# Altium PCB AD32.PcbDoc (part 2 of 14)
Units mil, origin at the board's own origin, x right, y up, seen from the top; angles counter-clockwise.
Board outline 7007.87 x 4368.85 mil, 12 copper layers (Top Layer, Int1 (GND), Int2 (AVDD), Int3 (DVDD), Int4 (GND), Int5 (ST), Int6 (SB), Int8 (AGND), Int7 (AVCC), Int9 (VCCA), Int10 (GND), Bottom Layer), stack 60.136 mil thick; 1350 components, 880 nets, 4712 pads, 2835 vias.
Unrouted connection lines stored in the file: 19.
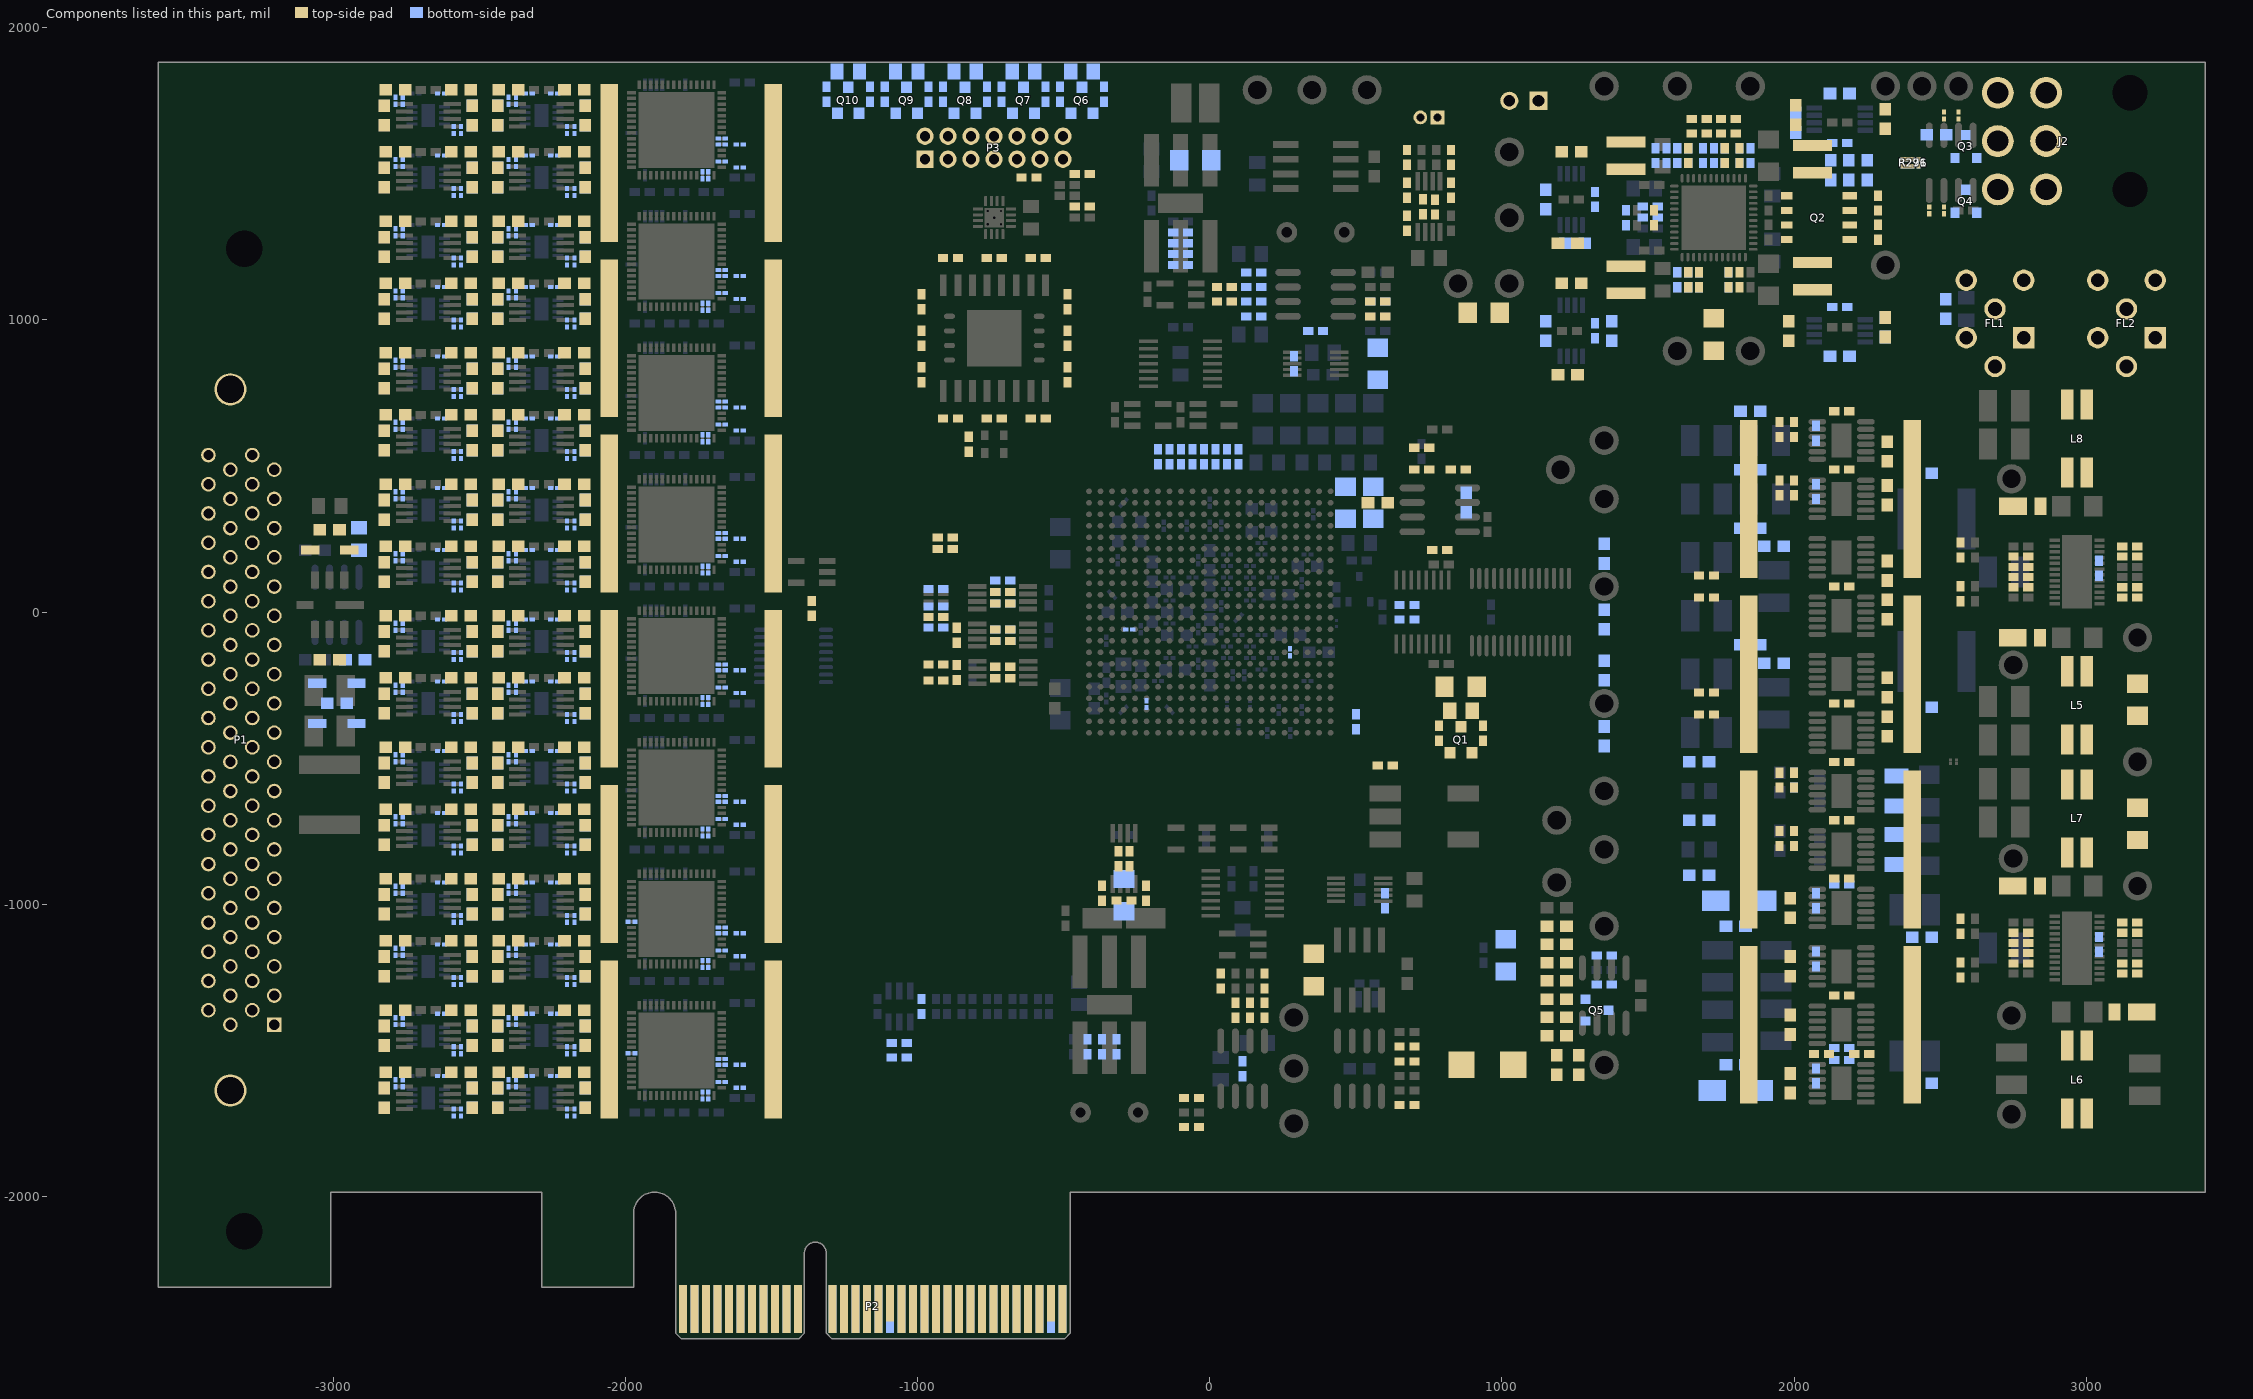
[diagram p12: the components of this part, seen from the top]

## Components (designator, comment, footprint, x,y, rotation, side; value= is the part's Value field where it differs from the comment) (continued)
C383G "1.0u" CC0603-0201 -1979.62,-1059.84 r180 bottom value=1u (schematic designator C383)
C383H "1.0u" CC0603-0201 -1979.62,-1509.84 r180 bottom value=1u (schematic designator C383)
C384A "100n" CC0603-0201 -2175,1437.5 r90 bottom (schematic designator C384)
C384B "100n" CC0603-0201 -2175,987.5 r90 bottom (schematic designator C384)
C384C "100n" CC0603-0201 -2175,537.5 r90 bottom (schematic designator C384)
C384D "100n" CC0603-0201 -2175,87.5 r90 bottom (schematic designator C384)
C384E "100n" CC0603-0201 -2175,-362.5 r90 bottom (schematic designator C384)
C384F "100n" CC0603-0201 -2175,-812.5 r90 bottom (schematic designator C384)
C384G "100n" CC0603-0201 -2175,-1262.5 r90 bottom (schematic designator C384)
C384H "100n" CC0603-0201 -2175,-1712.5 r90 bottom (schematic designator C384)
C385A "100n" CC0603-0201 -2200,1650 r90 bottom (schematic designator C385)
C385B "100n" CC0603-0201 -2200,1200 r90 bottom (schematic designator C385)
C385C "100n" CC0603-0201 -2200,750 r90 bottom (schematic designator C385)
C385D "100n" CC0603-0201 -2200,300 r90 bottom (schematic designator C385)
C385E "100n" CC0603-0201 -2200,-150 r90 bottom (schematic designator C385)
C385F "100n" CC0603-0201 -2200,-600 r90 bottom (schematic designator C385)
C385G "100n" CC0603-0201 -2200,-1050 r90 bottom (schematic designator C385)
C385H "100n" CC0603-0201 -2200,-1500 r90 bottom (schematic designator C385)
C400A "100n" CC0603-0201 -2400,1537.5 r90 bottom (schematic designator C400)
C400B "100n" CC0603-0201 -2400,1087.5 r90 bottom (schematic designator C400)
C400C "100n" CC0603-0201 -2400,637.5 r90 bottom (schematic designator C400)
C400D "100n" CC0603-0201 -2400,187.5 r90 bottom (schematic designator C400)
C400E "100n" CC0603-0201 -2400,-262.5 r90 bottom (schematic designator C400)
C400F "100n" CC0603-0201 -2400,-712.5 r90 bottom (schematic designator C400)
C400G "100n" CC0603-0201 -2400,-1162.5 r90 bottom (schematic designator C400)
C400H "100n" CC0603-0201 -2400,-1612.5 r90 bottom (schematic designator C400)
C401A "100n" CC0603-0201 -2400,1750 r90 bottom (schematic designator C401)
C401B "100n" CC0603-0201 -2400,1300 r90 bottom (schematic designator C401)
C401C "100n" CC0603-0201 -2400,850 r90 bottom (schematic designator C401)
C401D "100n" CC0603-0201 -2400,400 r90 bottom (schematic designator C401)
C401E "100n" CC0603-0201 -2400,-50 r90 bottom (schematic designator C401)
C401F "100n" CC0603-0201 -2400,-500 r90 bottom (schematic designator C401)
C401G "100n" CC0603-0201 -2400,-950 r90 bottom (schematic designator C401)
C401H "100n" CC0603-0201 -2400,-1400 r90 bottom (schematic designator C401)
C416A "100n" CC0603-0201 -2375,1750 r270 bottom (schematic designator C416)
C416B "100n" CC0603-0201 -2375,1300 r270 bottom (schematic designator C416)
C416C "100n" CC0603-0201 -2375,850 r270 bottom (schematic designator C416)
C416D "100n" CC0603-0201 -2375,400 r270 bottom (schematic designator C416)
C416E "100n" CC0603-0201 -2375,-50 r270 bottom (schematic designator C416)
C416F "100n" CC0603-0201 -2375,-500 r270 bottom (schematic designator C416)
C416G "100n" CC0603-0201 -2375,-950 r270 bottom (schematic designator C416)
C416H "100n" CC0603-0201 -2375,-1400 r270 bottom (schematic designator C416)
C424A "100n" CC0603-0201 -2375,1537.5 r270 bottom (schematic designator C424)
C424B "100n" CC0603-0201 -2375,1087.5 r270 bottom (schematic designator C424)
C424C "100n" CC0603-0201 -2375,637.5 r270 bottom (schematic designator C424)
C424D "100n" CC0603-0201 -2375,187.5 r270 bottom (schematic designator C424)
C424E "100n" CC0603-0201 -2375,-262.5 r270 bottom (schematic designator C424)
C424F "100n" CC0603-0201 -2375,-712.5 r270 bottom (schematic designator C424)
C424G "100n" CC0603-0201 -2375,-1162.5 r270 bottom (schematic designator C424)
C424H "100n" CC0603-0201 -2375,-1612.5 r270 bottom (schematic designator C424)
C432A "100n" CC0603-0201 -2175,1650 r270 bottom (schematic designator C432)
C432B "100n" CC0603-0201 -2175,1200 r270 bottom (schematic designator C432)
C432C "100n" CC0603-0201 -2175,750 r270 bottom (schematic designator C432)
C432D "100n" CC0603-0201 -2175,300 r270 bottom (schematic designator C432)
C432E "100n" CC0603-0201 -2175,-150 r270 bottom (schematic designator C432)
C432F "100n" CC0603-0201 -2175,-600 r270 bottom (schematic designator C432)
C432G "100n" CC0603-0201 -2175,-1050 r270 bottom (schematic designator C432)
C432H "100n" CC0603-0201 -2175,-1500 r270 bottom (schematic designator C432)
C440A "100n" CC0603-0201 -2200,1437.5 r270 bottom (schematic designator C440)
C440B "100n" CC0603-0201 -2200,987.5 r270 bottom (schematic designator C440)
C440C "100n" CC0603-0201 -2200,537.5 r270 bottom (schematic designator C440)
C440D "100n" CC0603-0201 -2200,87.5 r270 bottom (schematic designator C440)
C440E "100n" CC0603-0201 -2200,-362.5 r270 bottom (schematic designator C440)
C440F "100n" CC0603-0201 -2200,-812.5 r270 bottom (schematic designator C440)
C440G "100n" CC0603-0201 -2200,-1262.5 r270 bottom (schematic designator C440)
C440H "100n" CC0603-0201 -2200,-1712.5 r270 bottom (schematic designator C440)
C448A "100n" CC0603-0201 -2562.5,1437.5 r90 bottom (schematic designator C448)
C448B "100n" CC0603-0201 -2562.5,987.5 r90 bottom (schematic designator C448)
C448C "100n" CC0603-0201 -2562.5,537.5 r90 bottom (schematic designator C448)
C448D "100n" CC0603-0201 -2562.5,87.5 r90 bottom (schematic designator C448)
C448E "100n" CC0603-0201 -2562.5,-362.5 r90 bottom (schematic designator C448)
C448F "100n" CC0603-0201 -2562.5,-812.5 r90 bottom (schematic designator C448)
C448G "100n" CC0603-0201 -2562.5,-1262.5 r90 bottom (schematic designator C448)
C448H "100n" CC0603-0201 -2562.5,-1712.5 r90 bottom (schematic designator C448)
C449A "100n" CC0603-0201 -2587.5,1650 r90 bottom (schematic designator C449)
C449B "100n" CC0603-0201 -2587.5,1200 r90 bottom (schematic designator C449)
C449C "100n" CC0603-0201 -2587.5,750 r90 bottom (schematic designator C449)
C449D "100n" CC0603-0201 -2587.5,300 r90 bottom (schematic designator C449)
C449E "100n" CC0603-0201 -2587.5,-150 r90 bottom (schematic designator C449)
C449F "100n" CC0603-0201 -2587.5,-600 r90 bottom (schematic designator C449)
C449G "100n" CC0603-0201 -2587.5,-1050 r90 bottom (schematic designator C449)
C449H "100n" CC0603-0201 -2587.5,-1500 r90 bottom (schematic designator C449)
C464A "100n" CC0603-0201 -2787.5,1537.5 r90 bottom (schematic designator C464)
C464B "100n" CC0603-0201 -2787.5,1087.5 r90 bottom (schematic designator C464)
C464C "100n" CC0603-0201 -2787.5,637.5 r90 bottom (schematic designator C464)
C464D "100n" CC0603-0201 -2787.5,187.5 r90 bottom (schematic designator C464)
C464E "100n" CC0603-0201 -2787.5,-262.5 r90 bottom (schematic designator C464)
C464F "100n" CC0603-0201 -2787.5,-712.5 r90 bottom (schematic designator C464)
C464G "100n" CC0603-0201 -2787.5,-1162.5 r90 bottom (schematic designator C464)
C464H "100n" CC0603-0201 -2787.5,-1612.5 r90 bottom (schematic designator C464)
C465A "100n" CC0603-0201 -2787.5,1750 r90 bottom (schematic designator C465)
C465B "100n" CC0603-0201 -2787.5,1300 r90 bottom (schematic designator C465)
C465C "100n" CC0603-0201 -2787.5,850 r90 bottom (schematic designator C465)
C465D "100n" CC0603-0201 -2787.5,400 r90 bottom (schematic designator C465)
C465E "100n" CC0603-0201 -2787.5,-50 r90 bottom (schematic designator C465)
C465F "100n" CC0603-0201 -2787.5,-500 r90 bottom (schematic designator C465)
C465G "100n" CC0603-0201 -2787.5,-950 r90 bottom (schematic designator C465)
C465H "100n" CC0603-0201 -2787.5,-1400 r90 bottom (schematic designator C465)
C480A "100n" CC0603-0201 -2587.5,1437.5 r270 bottom (schematic designator C480)
C480B "100n" CC0603-0201 -2587.5,987.5 r270 bottom (schematic designator C480)
C480C "100n" CC0603-0201 -2587.5,537.5 r270 bottom (schematic designator C480)
C480D "100n" CC0603-0201 -2587.5,87.5 r270 bottom (schematic designator C480)
C480E "100n" CC0603-0201 -2587.5,-362.5 r270 bottom (schematic designator C480)
C480F "100n" CC0603-0201 -2587.5,-812.5 r270 bottom (schematic designator C480)
C480G "100n" CC0603-0201 -2587.5,-1262.5 r270 bottom (schematic designator C480)
C480H "100n" CC0603-0201 -2587.5,-1712.5 r270 bottom (schematic designator C480)
C488A "100n" CC0603-0201 -2762.5,1750 r270 bottom (schematic designator C488)
C488B "100n" CC0603-0201 -2762.5,1300 r270 bottom (schematic designator C488)
C488C "100n" CC0603-0201 -2762.5,850 r270 bottom (schematic designator C488)
C488D "100n" CC0603-0201 -2762.5,400 r270 bottom (schematic designator C488)
C488E "100n" CC0603-0201 -2762.5,-50 r270 bottom (schematic designator C488)
C488F "100n" CC0603-0201 -2762.5,-500 r270 bottom (schematic designator C488)
C488G "100n" CC0603-0201 -2762.5,-950 r270 bottom (schematic designator C488)
C488H "100n" CC0603-0201 -2762.5,-1400 r270 bottom (schematic designator C488)
C496A "100n" CC0603-0201 -2762.5,1537.5 r270 bottom (schematic designator C496)
C496B "100n" CC0603-0201 -2762.5,1087.5 r270 bottom (schematic designator C496)
C496C "100n" CC0603-0201 -2762.5,637.5 r270 bottom (schematic designator C496)
C496D "100n" CC0603-0201 -2762.5,187.5 r270 bottom (schematic designator C496)
C496E "100n" CC0603-0201 -2762.5,-262.5 r270 bottom (schematic designator C496)
C496F "100n" CC0603-0201 -2762.5,-712.5 r270 bottom (schematic designator C496)
C496G "100n" CC0603-0201 -2762.5,-1162.5 r270 bottom (schematic designator C496)
C496H "100n" CC0603-0201 -2762.5,-1612.5 r270 bottom (schematic designator C496)
C504A "100n" CC0603-0201 -2562.5,1650 r270 bottom (schematic designator C504)
C504B "100n" CC0603-0201 -2562.5,1200 r270 bottom (schematic designator C504)
C504C "100n" CC0603-0201 -2562.5,750 r270 bottom (schematic designator C504)
C504D "100n" CC0603-0201 -2562.5,300 r270 bottom (schematic designator C504)
C504E "100n" CC0603-0201 -2562.5,-150 r270 bottom (schematic designator C504)
C504F "100n" CC0603-0201 -2562.5,-600 r270 bottom (schematic designator C504)
C504G "100n" CC0603-0201 -2562.5,-1050 r270 bottom (schematic designator C504)
C504H "100n" CC0603-0201 -2562.5,-1500 r270 bottom (schematic designator C504)
C512 "100n" CC2013-0805 -2912.5,250 r90 bottom
D1 "DIODE" DO-SOD123 -2987.5,-243.75 r180 bottom
D2 "DIODE" DO-SOD123 -2987.5,-381.25 r0 bottom
D3 "NS" DO-SOD123 -3012.5,212.5 r180 top
D4 "Schottky SMB" DO-SMB 950,-1550 r0 top
D5 "Schottky DO-PowerDI123" DO-PowerDI123 2781.21,-937.5 r180 top
D6 "Schottky DO-PowerDI123" DO-PowerDI123 2781.25,-87.5 r180 top
D7 "Schottky DO-PowerDI123" DO-PowerDI123 2782.5,362.5 r180 top
D8 "Schottky DO-PowerDI123" DO-PowerDI123 3156.25,-1368.75 r0 top
D9 "shottky diode" DO-SMA 1812.5,-987.5 r180 bottom
D10 "shottky diode" DO-SMA 1800,-1637.5 r0 bottom
DS1 "LED" LED-0805 860,-337.5 r0 top
DS2 "LED" LED-0805 -437.5,1850 r180 bottom
DS3 "LED" LED-0805 -637.5,1850 r180 bottom
DS4 "LED" LED-0805 -837.5,1850 r180 bottom
DS5 "LED" LED-0805 -1037.5,1850 r180 bottom
DS6 "LED" LED-0805 -1237.5,1850 r180 bottom
FL1 "BNX016-01" FP-BNX_L12MM2_W11MM2_T8MM-MFG 2687.5,1037.5 r270 top locked
FL2 "BNX016-01" FP-BNX_L12MM2_W11MM2_T8MM-MFG 3137.5,1037.5 r270 top
FR1 "BLM31PG121" CC3216-1206 356.25,-1225 r270 top
FR2 "BLM31PG121" CC3216-1206 858.27,-255.91 r0 top
FR3 "BLM31PG121" CC3216-1206 937.5,1025 r180 top
FR4 "BLM31PG121" CC3216-1206 1725,950 r270 top
FR5 "BLM31PG121" CC3216-1206 3175,-725 r270 top
FR6 "BLM31PG121" CC3216-1206 3175,-300 r90 top
FR7 "BLM31PG121" CC3216-1206 1012.5,-1175 r90 bottom
FR8 "BLM31PG121" CC3216-1206 575,850 r270 bottom
FR9 "BLM31PG121" CC3216-1206 559.06,374.02 r270 bottom
FR10 "BLM31PG121" CC3216-1206 464.57,374.02 r270 bottom
FR11 "BLM31PG121" CC3216-1206 -50,1546.74 r0 bottom
FR12 "BLM31PG121" CC3216-1206 -293.75,-968.75 r90 bottom
J1 "S2B-ZR(LF)(SN)" FP-S2B-ZR_LF_SN-MFG 750,1756.25 r180 top
J2 "45558-0003" 455580003 2862.5,1777.5 r270 top
L1 "XFL4020-222MEC" FP-XFL4020-MFG 1425,1137.5 r270 top
L2 "XFL4020-222MEC" FP-XFL4020-MFG 1425,1562.5 r90 top
L3 "XFL4020-332MEB" FP-XFL4020-MFG 2062.5,1150 r270 top
L4 "XFL4020-472" FP-XAL40-MFG 2062.5,1550 r90 top value=4.7uH
L5 "4.7uH" MSD7342 2935,-212.5 r0 top
L6 "8.2uH" MSD7342 2935.25,-1493.5 r0 top
L7 "8.2uH" MSD7342 3002.25,-812.75 r180 top
L8 "8.2uH" MSD7342 3002.25,487.25 r180 top
L9 "33nH" CL2520-1008 2350,-812.5 r270 bottom
L10 "100nH" CL2520-1008 2350,-612.5 r270 bottom
LOGO1 "LIGO logo" LIGO-LOGO-SM -3418.75,1725.4 r0 top value=NL
MP1 "DA-T263-201E-TR" FP-DA-T263-201E-TR-MFG -1775,-1462.5 r0 top locked
MP2 "DA-T263-201E-TR" FP-DA-T263-201E-TR-MFG -1775,-862.5 r0 top locked
MP3 "DA-T263-201E-TR" FP-DA-T263-201E-TR-MFG -1775,-262.5 r0 top locked
MP4 "DA-T263-201E-TR" FP-DA-T263-201E-TR-MFG -1775,337.5 r0 top locked
MP5 "DA-T263-201E-TR" FP-DA-T263-201E-TR-MFG -1775,937.5 r0 top locked
MP6 "DA-T263-201E-TR" FP-DA-T263-201E-TR-MFG -1775,1537.5 r0 top locked
MP7 "DA-T263-201E-TR" FP-DA-T263-201E-TR-MFG 2125,-1412.5 r0 top
MP8 "DA-T263-201E-TR" FP-DA-T263-201E-TR-MFG 2125,-812.5 r0 top
MP9 "DA-T263-201E-TR" FP-DA-T263-201E-TR-MFG 2125,-212.5 r0 top
MP10 "DA-T263-201E-TR" FP-DA-T263-201E-TR-MFG 2125,387.5 r0 top
P1 "P50E-080P1-RR1EA" P50E-080-SR1 -3302.3,-1437.5 r270 top locked
P2 "PCIeX4-GF-2D-1000-1K-O64" PCIeX4-GF-2D-1000-1K-O64 -1429.06,-2385 r0 top value=NL
P3 "2mm Header 2x7" 2MM_HDR2X7_RA -975,1550 r0 top locked
P4 "Header 2" WM4200 1125,1750 r180 top
Q1 "FDV301N" SO-G3/C2.25 860,-437.5 r0 top
Q2 "AON6816" VISH-POWERPAKSO-8_A_V 2085.04,1350 r180 top
Q3 "MMBT3906LT1G" ONSC-SOT-23-3-318-08_V 2587.5,1593.75 r90 bottom
Q4 "MMBT3906LT1G" ONSC-SOT-23-3-318-08_V 2587.5,1406.25 r90 bottom
Q5 "MMBT3906LT1G" ONSC-SOT-23-3-318-08_V 1325,-1362.5 r0 bottom
Q6 "FDV301N" SO-G3/C2.25 -437.5,1752.5 r180 bottom
Q7 "FDV301N" SO-G3/C2.25 -637.5,1752.5 r180 bottom
Q8 "FDV301N" SO-G3/C2.25 -837.5,1752.5 r180 bottom
Q9 "FDV301N" SO-G3/C2.25 -1037.5,1752.5 r180 bottom
Q10 "FDV301N" SO-G3/C2.25 -1237.5,1752.5 r180 bottom
R1 "10k" CR1608-0603 -2987.5,-312.5 r0 bottom
R2 "0" CR1608-0603 -3012.5,281.25 r0 top
R3 "680" CR1608-0603 -2925,-162.5 r180 bottom
R4A "2.05k" CR1608-0603 -2825,1700 r90 top (schematic designator R4)
R4B "2.05k" CR1608-0603 -2825,1250 r90 top (schematic designator R4)
R4C "2.05k" CR1608-0603 -2825,800 r90 top (schematic designator R4)
R4D "2.05k" CR1608-0603 -2825,350 r90 top (schematic designator R4)
R4E "2.05k" CR1608-0603 -2825,-100 r90 top (schematic designator R4)
R4F "2.05k" CR1608-0603 -2825,-550 r90 top (schematic designator R4)
R4G "2.05k" CR1608-0603 -2825,-1000 r90 top (schematic designator R4)
R4H "2.05k" CR1608-0603 -2825,-1450 r90 top (schematic designator R4)
R5 "49.9" CR1005-0402 -436.25,1387.5 r0 top
R6 "NL" CR1005-0402 -618.75,1487.5 r180 top
R7 "49.9" CR1005-0402 -436.25,1500 r180 top
R8 "0" CR1608-0603 -3012.5,-162.5 r0 top
R12A "2.05k" CR1608-0603 -2825,1487.5 r90 top (schematic designator R12)
R12B "2.05k" CR1608-0603 -2825,1037.5 r90 top (schematic designator R12)
R12C "2.05k" CR1608-0603 -2825,587.5 r90 top (schematic designator R12)
R12D "2.05k" CR1608-0603 -2825,137.5 r90 top (schematic designator R12)
R12E "2.05k" CR1608-0603 -2825,-312.5 r90 top (schematic designator R12)
R12F "2.05k" CR1608-0603 -2825,-762.5 r90 top (schematic designator R12)
R12G "2.05k" CR1608-0603 -2825,-1212.5 r90 top (schematic designator R12)
R12H "2.05k" CR1608-0603 -2825,-1662.5 r90 top (schematic designator R12)
R20A "100" CR1608-0603 -2787.5,1787.5 r0 top (schematic designator R20)
R20B "100" CR1608-0603 -2787.5,1337.5 r0 top (schematic designator R20)
R20C "100" CR1608-0603 -2787.5,887.5 r0 top (schematic designator R20)
R20D "100" CR1608-0603 -2787.5,437.5 r0 top (schematic designator R20)
R20E "100" CR1608-0603 -2787.5,-12.5 r0 top (schematic designator R20)
R20F "100" CR1608-0603 -2787.5,-462.5 r0 top (schematic designator R20)
R20G "100" CR1608-0603 -2787.5,-912.5 r0 top (schematic designator R20)
R20H "100" CR1608-0603 -2787.5,-1362.5 r0 top (schematic designator R20)
R28A "100" CR1608-0603 -2787.5,1575 r0 top (schematic designator R28)
R28B "100" CR1608-0603 -2787.5,1125 r0 top (schematic designator R28)
R28C "100" CR1608-0603 -2787.5,675 r0 top (schematic designator R28)
R28D "100" CR1608-0603 -2787.5,225 r0 top (schematic designator R28)
R28E "100" CR1608-0603 -2787.5,-225 r0 top (schematic designator R28)
R28F "100" CR1608-0603 -2787.5,-675 r0 top (schematic designator R28)
R28G "100" CR1608-0603 -2787.5,-1125 r0 top (schematic designator R28)
R28H "100" CR1608-0603 -2787.5,-1575 r0 top (schematic designator R28)
R36A "100" CR1608-0603 -2562.5,1787.5 r180 top (schematic designator R36)
R36B "100" CR1608-0603 -2562.5,1337.5 r180 top (schematic designator R36)
R36C "100" CR1608-0603 -2562.5,887.5 r180 top (schematic designator R36)
R36D "100" CR1608-0603 -2562.5,437.5 r180 top (schematic designator R36)
R36E "100" CR1608-0603 -2562.5,-12.5 r180 top (schematic designator R36)
R36F "100" CR1608-0603 -2562.5,-462.5 r180 top (schematic designator R36)
R36G "100" CR1608-0603 -2562.5,-912.5 r180 top (schematic designator R36)
R36H "100" CR1608-0603 -2562.5,-1362.5 r180 top (schematic designator R36)
R44A "100" CR1608-0603 -2562.5,1575 r180 top (schematic designator R44)
R44B "100" CR1608-0603 -2562.5,1125 r180 top (schematic designator R44)
R44C "100" CR1608-0603 -2562.5,675 r180 top (schematic designator R44)
R44D "100" CR1608-0603 -2562.5,225 r180 top (schematic designator R44)
R44E "100" CR1608-0603 -2562.5,-225 r180 top (schematic designator R44)
R44F "100" CR1608-0603 -2562.5,-675 r180 top (schematic designator R44)
R44G "100" CR1608-0603 -2562.5,-1125 r180 top (schematic designator R44)
R44H "100" CR1608-0603 -2562.5,-1575 r180 top (schematic designator R44)
R52A "2.05k" CR1608-0603 -2525,1700 r90 top (schematic designator R52)
R52B "2.05k" CR1608-0603 -2525,1250 r90 top (schematic designator R52)
R52C "2.05k" CR1608-0603 -2525,800 r90 top (schematic designator R52)
R52D "2.05k" CR1608-0603 -2525,350 r90 top (schematic designator R52)
R52E "2.05k" CR1608-0603 -2525,-100 r90 top (schematic designator R52)
R52F "2.05k" CR1608-0603 -2525,-550 r90 top (schematic designator R52)
R52G "2.05k" CR1608-0603 -2525,-1000 r90 top (schematic designator R52)
R52H "2.05k" CR1608-0603 -2525,-1450 r90 top (schematic designator R52)
R60A "2.05k" CR1608-0603 -2525,1487.5 r90 top (schematic designator R60)
R60B "2.05k" CR1608-0603 -2525,1037.5 r90 top (schematic designator R60)
R60C "2.05k" CR1608-0603 -2525,587.5 r90 top (schematic designator R60)
R60D "2.05k" CR1608-0603 -2525,137.5 r90 top (schematic designator R60)
R60E "2.05k" CR1608-0603 -2525,-312.5 r90 top (schematic designator R60)
R60F "2.05k" CR1608-0603 -2525,-762.5 r90 top (schematic designator R60)
R60G "2.05k" CR1608-0603 -2525,-1212.5 r90 top (schematic designator R60)
R60H "2.05k" CR1608-0603 -2525,-1662.5 r90 top (schematic designator R60)
R68A "2.05k" CR1608-0603 -2437.5,1700 r90 top (schematic designator R68)
R68B "2.05k" CR1608-0603 -2437.5,1250 r90 top (schematic designator R68)
R68C "2.05k" CR1608-0603 -2437.5,800 r90 top (schematic designator R68)
R68D "2.05k" CR1608-0603 -2437.5,350 r90 top (schematic designator R68)
R68E "2.05k" CR1608-0603 -2437.5,-100 r90 top (schematic designator R68)
R68F "2.05k" CR1608-0603 -2437.5,-550 r90 top (schematic designator R68)
R68G "2.05k" CR1608-0603 -2437.5,-1000 r90 top (schematic designator R68)
R68H "2.05k" CR1608-0603 -2437.5,-1450 r90 top (schematic designator R68)
R76A "2.05k" CR1608-0603 -2437.5,1487.5 r90 top (schematic designator R76)
R76B "2.05k" CR1608-0603 -2437.5,1037.5 r90 top (schematic designator R76)
R76C "2.05k" CR1608-0603 -2437.5,587.5 r90 top (schematic designator R76)
R76D "2.05k" CR1608-0603 -2437.5,137.5 r90 top (schematic designator R76)
R76E "2.05k" CR1608-0603 -2437.5,-312.5 r90 top (schematic designator R76)
R76F "2.05k" CR1608-0603 -2437.5,-762.5 r90 top (schematic designator R76)
R76G "2.05k" CR1608-0603 -2437.5,-1212.5 r90 top (schematic designator R76)
R76H "2.05k" CR1608-0603 -2437.5,-1662.5 r90 top (schematic designator R76)
R84A "100" CR1608-0603 -2400,1787.5 r0 top (schematic designator R84)
R84B "100" CR1608-0603 -2400,1337.5 r0 top (schematic designator R84)
R84C "100" CR1608-0603 -2400,887.5 r0 top (schematic designator R84)
R84D "100" CR1608-0603 -2400,437.5 r0 top (schematic designator R84)
R84E "100" CR1608-0603 -2400,-12.5 r0 top (schematic designator R84)
R84F "100" CR1608-0603 -2400,-462.5 r0 top (schematic designator R84)
R84G "100" CR1608-0603 -2400,-912.5 r0 top (schematic designator R84)
R84H "100" CR1608-0603 -2400,-1362.5 r0 top (schematic designator R84)
R92A "100" CR1608-0603 -2400,1575 r0 top (schematic designator R92)
R92B "100" CR1608-0603 -2400,1125 r0 top (schematic designator R92)
R92C "100" CR1608-0603 -2400,675 r0 top (schematic designator R92)
R92D "100" CR1608-0603 -2400,225 r0 top (schematic designator R92)
R92E "100" CR1608-0603 -2400,-225 r0 top (schematic designator R92)
R92F "100" CR1608-0603 -2400,-675 r0 top (schematic designator R92)
R92G "100" CR1608-0603 -2400,-1125 r0 top (schematic designator R92)
R92H "100" CR1608-0603 -2400,-1575 r0 top (schematic designator R92)
R100A "100" CR1608-0603 -2175,1787.5 r180 top (schematic designator R100)
R100B "100" CR1608-0603 -2175,1337.5 r180 top (schematic designator R100)
R100C "100" CR1608-0603 -2175,887.5 r180 top (schematic designator R100)
R100D "100" CR1608-0603 -2175,437.5 r180 top (schematic designator R100)
R100E "100" CR1608-0603 -2175,-12.5 r180 top (schematic designator R100)
R100F "100" CR1608-0603 -2175,-462.5 r180 top (schematic designator R100)
R100G "100" CR1608-0603 -2175,-912.5 r180 top (schematic designator R100)
R100H "100" CR1608-0603 -2175,-1362.5 r180 top (schematic designator R100)
R108A "100" CR1608-0603 -2175,1575 r180 top (schematic designator R108)
R108B "100" CR1608-0603 -2175,1125 r180 top (schematic designator R108)
R108C "100" CR1608-0603 -2175,675 r180 top (schematic designator R108)
R108D "100" CR1608-0603 -2175,225 r180 top (schematic designator R108)
R108E "100" CR1608-0603 -2175,-225 r180 top (schematic designator R108)
R108F "100" CR1608-0603 -2175,-675 r180 top (schematic designator R108)
R108G "100" CR1608-0603 -2175,-1125 r180 top (schematic designator R108)
R108H "100" CR1608-0603 -2175,-1575 r180 top (schematic designator R108)
R116A "2.05k" CR1608-0603 -2137.5,1700 r90 top (schematic designator R116)
R116B "2.05k" CR1608-0603 -2137.5,1250 r90 top (schematic designator R116)
R116C "2.05k" CR1608-0603 -2137.5,800 r90 top (schematic designator R116)
R116D "2.05k" CR1608-0603 -2137.5,350 r90 top (schematic designator R116)
R116E "2.05k" CR1608-0603 -2137.5,-100 r90 top (schematic designator R116)
R116F "2.05k" CR1608-0603 -2137.5,-550 r90 top (schematic designator R116)
R116G "2.05k" CR1608-0603 -2137.5,-1000 r90 top (schematic designator R116)
R116H "2.05k" CR1608-0603 -2137.5,-1450 r90 top (schematic designator R116)
R124A "2.05k" CR1608-0603 -2137.5,1487.5 r90 top (schematic designator R124)
R124B "2.05k" CR1608-0603 -2137.5,1037.5 r90 top (schematic designator R124)
R124C "2.05k" CR1608-0603 -2137.5,587.5 r90 top (schematic designator R124)
R124D "2.05k" CR1608-0603 -2137.5,137.5 r90 top (schematic designator R124)
R124E "2.05k" CR1608-0603 -2137.5,-312.5 r90 top (schematic designator R124)
R124F "2.05k" CR1608-0603 -2137.5,-762.5 r90 top (schematic designator R124)
R124G "2.05k" CR1608-0603 -2137.5,-1212.5 r90 top (schematic designator R124)
R124H "2.05k" CR1608-0603 -2137.5,-1662.5 r90 top (schematic designator R124)
R132 "100" CR1005-0402 -1362.5,12.5 r90 top
R133 "1.8k" CR1005-0402 -987.5,812.5 r270 top
R134 "1.8k" CR1005-0402 -987.5,937.5 r270 top
R135 "NL" CR1005-0402 -987.5,1062.5 r270 top
R136 "NL" CR1005-0402 -937.5,-178.9 r180 top
R137 "NL" CR1005-0402 -937.5,-233.9 r0 top
R138 "NL" CR1005-0402 -937.48,-16.3 r180 top
R139 "NL" CR1005-0402 -905.51,216.54 r180 top locked
R140 "1.0k" CR1005-0402 -905.51,255.91 r180 top locked
R141 "100" CR1005-0402 -887.5,662.5 r0 top
R142 "NL" CR1005-0402 -887.5,1212.5 r0 top
R143 "NL" CR1005-0402 -866.14,-206.69 r90 top locked
R144 "100" CR1005-0402 -866.14,-78.74 r270 top locked
R145 "4.7k" CR1005-0402 -825,575 r270 top
R146 "1.8k" CR1005-0402 -737.5,662.5 r0 top
R147 "100" CR1005-0402 -737.5,1212.5 r0 top
R148 "NL" CR1005-0402 -708.66,-226.38 r180 top
R149 "NL" CR1005-0402 -708.66,-187.01 r180 top
R150 "NL" CR1005-0402 -708.66,-98.43 r0 top
R151 "NL" CR1005-0402 -708.66,-59.06 r0 top
R152 "NL" CR1005-0402 -708.66,29.53 r0 top
R153 "NL" CR1005-0402 -708.66,68.9 r0 top
R154 "100" CR1005-0402 -587.5,1212.5 r180 top
R155 "4.7k" CR1005-0402 -587.5,662.5 r0 top
R156 "100" CR0603-0201 -216.54,-314.96 r270 bottom
R157 "100" CR0603-0201 -275.59,-59.06 r180 bottom
R158 "1.8k" CR1005-0402 -487.5,812.5 r270 top
R159 "100" CR1005-0402 -487.5,937.5 r90 top
R160 "1.8k" CR1005-0402 -487.5,1062.5 r90 top
R161 "NL" CR1005-0402 -318.75,-1487.5 r90 bottom
R162 "NL" CR1005-0402 -368.75,-962.5 r270 top
R163 "NL" CR1005-0402 -293.75,-987.5 r0 top
R164 "NL" CR1005-0402 -312.5,-843.75 r270 top
R165 "NL" CR1005-0402 -368.75,-1487.5 r270 bottom
R166 "NL" CR1005-0402 -275,-843.75 r90 top
R167 "NL" CR1005-0402 -218.75,-962.5 r90 top
R168 "10k" CR1005-0402 -62.5,-1662.5 r180 top
R169 "1.0K" CR1005-0402 -62.5,-1762.5 r0 top value=1.0k
R170 "10k" CR1005-0402 50,1062.5 r0 top
R171 "10k" CR1005-0402 50,1112.5 r0 top
R172 "10K" CR1005-0402 37.5,-1262.5 r270 top value=10k
R173 "10K" CR1005-0402 87.5,-1362.5 r270 top value=10k
R174 "10K" CR1005-0402 137.5,-1362.5 r270 top value=10k
R175 "15K" CR1005-0402 187.5,-1362.5 r270 top
R176 "10K" CR1005-0402 187.5,-1262.5 r270 top value=10k
R177 "1k" CR1608-0603 575,375 r0 top
R178 "10k" CR1005-0402 575,1012.5 r0 top
R179 "10k" CR1005-0402 575,1062.5 r0 top
R180 "15K" CR1005-0402 675,-1687.5 r180 top
R181 "10K" CR1005-0402 675,-1537.5 r0 top value=10k
R182 "10K" CR1005-0402 675,-1487.5 r0 top value=10k
R183 "22K" CR1005-0402 675,1331.25 r270 top
R184 "49.9" CR1005-0402 675,1443.75 r90 top
R185 "2.32K" CR1005-0402 675,1556.25 r90 top
R186 "200K" CR1005-0402 725,562.5 r180 top
R187 "2K" CR1005-0402 725,487.5 r0 top
R188 "NL" CR1005-0402 730,1387.5 r270 top
R189 "2K" CR1005-0402 787.5,212.5 r0 top
R190 "NL" CR1005-0402 770,1386.25 r270 top
R191 "4.7k" CR1005-0402 785,-415 r90 top
R192 "200K" CR1005-0402 850,487.5 r0 top
R193 "49.9" CR1005-0402 825,1443.75 r270 top
R194 "1.6K" CR1005-0402 825,1556.25 r270 top
R195 "1.0k" CR1005-0402 935,-415 r90 top
R196 "220" CR1608-0603 1225,812.5 r180 top
R197 "10K" CR1608-0603 1375,962.5 r270 bottom
R198 "1.37K" CR1608-0603 1187.5,-1387.5 r180 top
R199 "220" CR1608-0603 1187.5,-1325 r180 top
R200 "220" CR1608-0603 1187.5,-1262.5 r180 top
R201 "220" CR1608-0603 1187.5,-1200 r180 top
R202 "59K" CR1608-0603 1187.5,-1137.5 r180 top
R203 "1K" CR1608-0603 1187.5,-1075 r180 top
R204 "3.7K" CR1608-0603 1187.5,-1450 r0 top
R205 "100" CR1005-0402 1318.75,962.5 r90 bottom
R206 "100" CR1005-0402 1318.75,1412.5 r90 bottom
R207 "59K" CR1608-0603 1187.5,-1550 r270 top
R208 "220" CR1608-0603 1225,1262.5 r180 top
R209 "10K" CR1608-0603 1250,1262.5 r0 bottom
R210 "10m" CR1608-0603 1237.5,1125 r0 top
R211 "10m" CR1608-0603 1237.5,1575 r0 top
R212 "1K" CR1608-0603 1262.5,-1550 r90 top
R213 "5.23k" CR1608-0603 1150,962.5 r90 bottom
R214 "5.23k" CR1608-0603 1150,1412.5 r90 bottom
R215 "4.99k" CR1005-0402 1520,1350 r270 top
R216 "15k" CR1005-0402 1637.5,1137.5 r90 top
R217 "9.31k" CR1005-0402 1637.5,1562.5 r270 top
R218 "21.5k" CR1005-0402 1675,1687.5 r180 top
R219 "10k" CR1005-0402 1675,1637.5 r0 top
R220 "22k" CR1005-0402 1700,-350 r0 top
R221 "100K" CR1005-0402 1700,-275 r0 top
R222 "22K" CR1005-0402 1700,50 r0 top
R223 "100K" CR1005-0402 1700,125 r0 top
R224 "31.6k" CR1005-0402 1675,1137.5 r270 top
R225 "10k" CR1005-0402 1775,1637.5 r180 top
R226 "12.7k" CR1005-0402 1775,1687.5 r0 top
R227 "37.4k" CR1005-0402 1762.5,1562.5 r90 top
R228 "10k" CR1005-0402 1775,1137.5 r270 top
R229 "7.15k" CR1005-0402 1812.5,1137.5 r90 top
R230 "56.2k" CR1005-0402 1812.5,1562.5 r270 top
R231 "9.09k" CR1608-0603 1931.25,-175 r180 bottom
R232 "9.09k" CR1608-0603 1931.25,225 r0 bottom
R233 "220" CR1608-0603 2006.25,1701.25 r90 top
R234 "130K" CR1005-0402 1950,-775 r270 top
R235 "100K" CR1005-0402 1950,-575 r270 top
R236 "10m" CR1608-0603 1987.5,-1612.5 r270 top
R237 "10m" CR1608-0603 1987.5,-1412.5 r270 top
R238 "10m" CR1608-0603 1987.5,-1212.5 r270 top
R239 "10m" CR1608-0603 1987.5,-1012.5 r270 top
R240 "10K" CR1608-0603 2006.25,1675 r270 bottom
R241 "49.9k" CR1005-0402 2000,-775 r90 top
R242 "49.9k" CR1005-0402 2000,-575 r90 top
R243 "10m" CR1608-0603 1981.25,962.5 r90 top
R244 "267K" CR1005-0402 2093.75,-1512.5 r180 top
R245 "5.23k" CR1608-0603 2156.25,1775 r0 bottom
R246 "100" CR1005-0402 2156.25,1606.25 r0 bottom
R247 "150" CR1005-0402 2162.5,-312.5 r180 top
R248 "150" CR1005-0402 2162.5,87.5 r180 top
R249 "300" CR1005-0402 2162.5,487.5 r180 top
R250 "300" CR1005-0402 2162.5,687.5 r180 top
R251 "249K" CR1005-0402 2162.5,-1312.5 r0 top
R252 "150" CR1005-0402 2162.5,-912.5 r0 top
R253 "300" CR1005-0402 2162.5,-712.5 r0 top
R254 "300" CR1005-0402 2162.5,-512.5 r0 top
R255 "5.23k" CR1608-0603 2156.25,875 r180 bottom
R256 "100" CR1005-0402 2156.25,1043.75 r180 bottom
R257 "150" CR1005-0402 2231.25,-1512.5 r180 top
R258 "47k" CR1005-0402 2287.5,1300 r270 top
R259 "NL" CR1005-0402 2287.5,1400 r270 top
R260 "10m" CR1608-0603 2312.5,1687.5 r270 top
R261 "10m" CR1608-0603 2318.75,-391.54 r90 top
R262 "10m" CR1608-0603 2318.75,-258.46 r270 top
R263 "10m" CR1608-0603 2318.75,8.46 r90 top
R264 "10m" CR1608-0603 2318.75,141.54 r270 top
R265 "10m" CR1608-0603 2318.75,400 r90 top
R266 "10m" CR1608-0603 2318.75,550 r270 top
R267 "10K" CR1608-0603 2312.5,975 r90 bottom
R268 "220" CR1608-0603 2312.5,975 r270 top
R269 "1K" CR0603-0201 2512.5,1700 r90 top
R270 "1K" CR0603-0201 2462.5,1375 r90 top
R271 "0.01" CR0816-0306-4P 2398.75,1537.5 r270 top
R272 "1K" CR0603-0201 2562.5,1700 r90 top
R273 "162K" CR1005-0402 2568.75,-1225 r90 top
R274 "162K" CR1005-0402 2568.75,-1075 r90 top
R275 "15.6k" CR1005-0402 2568.75,62.5 r90 top
R276 "57.6K" CR1005-0402 2568.75,212.5 r90 top
R277 "2K" CR1005-0402 2776.25,-1202.5 r180 top
R278 "2K" CR1005-0402 2776.25,85 r180 top
R279 "14.7K" CR1005-0402 2776.25,-1167.5 r0 top
R280 "0" CR1005-0402 2776.25,-1132.5 r0 top
R281 "2K" CR1005-0402 2776.25,-1097.5 r0 top
R282 "0" CR1005-0402 2776.25,120 r0 top
R283 "0" CR1005-0402 2776.25,155 r0 top
R284 "2K" CR1005-0402 2776.25,190 r0 top
R285 "76.8K" CR1005-0402 3148.75,-1097.5 r180 top
R286 "76.8K" CR1005-0402 3148.75,190 r180 top
R287 "715K" CR1005-0402 3148.75,-1237.5 r0 top
R288 "76.8K" CR1005-0402 3148.75,-1202.5 r0 top
R289 "715K" CR1005-0402 3148.75,-1062.5 r0 top
R290 "715K" CR1005-0402 3148.75,50 r0 top
R291 "76.8K" CR1005-0402 3148.75,85 r0 top
R292 "715K" CR1005-0402 3148.75,225 r0 top
R293 "4.7k" CR1005-0402 3043.75,-1137.5 r90 bottom
R294 "4.7k" CR1005-0402 3043.75,150 r90 bottom
R295 "15K" CR1608-0603 2487.5,1633.12 r0 bottom
R296 "0.01" CR0816-0306-4P 2398.75,1537.5 r90 bottom
R297 "1K" CR0603-0201 2512.5,1375 r90 top
R298 "10m" CR1608-0603 2518.75,1037.5 r270 bottom
R299 "0" CR1608-0603 2437.5,-1612.5 r0 bottom
R300 "0" CR1608-0603 2437.5,-1112.5 r0 bottom
R301 "10m" CR1608-0603 2437.5,-325 r0 bottom
R302 "10m" CR1608-0603 2437.5,475 r0 bottom
R303 "59K" CR1608-0603 2250,1512.5 r270 bottom
R304 "1K" CR1608-0603 2187.5,1512.5 r90 bottom
R305 "2.32k" CR1005-0402 2162.5,-1532.5 r0 bottom
R306 "100K" CR1005-0402 2162.5,-1492.5 r0 bottom
R307 "2.32k" CR1005-0402 2162.5,-932.5 r0 bottom
R308 "220" CR1608-0603 2125,1512.5 r90 bottom
R309 "56.2k" CR1005-0402 2075,-1587.5 r270 bottom
R310 "56.2k" CR1005-0402 2075,-1187.5 r90 bottom
R311 "100K" CR1005-0402 2075,-987.5 r90 bottom
R312 "49.9k" CR1005-0402 2075,412.5 r90 bottom
R313 "49.9k" CR1005-0402 2075,612.5 r90 bottom
R314 "12.1K" CR1005-0402 2000,-775 r90 bottom
R315 "10K" CR1005-0402 2000,-575 r90 bottom value=10k
R316 "22k" CR1005-0402 2000,425 r270 top
R317 "22k" CR1005-0402 2000,625 r270 top
R318 "330K" CR1005-0402 1950,425 r90 top
R319 "330K" CR1005-0402 1950,625 r90 top
R320 "220" CR1608-0603 1850,-112.5 r180 bottom
R321 "220" CR1608-0603 1850,287.5 r180 bottom
R322 "220" CR1608-0603 1850,487.5 r180 bottom
R323 "220" CR1608-0603 1850,687.5 r180 bottom
R324 "0" CR1005-0402 1850,1562.5 r270 bottom
R325 "1K" CR1608-0603 1837.5,-1450 r90 bottom
R326 "10m" CR1608-0603 1800,-1550 r0 bottom
R327 "10m" CR1608-0603 1800,-1075 r0 bottom
R328 "NL" CR1005-0402 1812.5,1562.5 r90 bottom
R329 "40.2k" CR1005-0402 1775,1137.5 r270 bottom
R330 "0" CR1005-0402 1762.5,1562.5 r90 bottom
R331 "NL" CR1005-0402 1725,1562.5 r90 bottom
R332 "220" CR1608-0603 1675,-900 r180 bottom
R333 "220" CR1608-0603 1675,-712.5 r180 bottom
R334 "220" CR1608-0603 1675,-512.5 r180 bottom
R335 "NL" CR1005-0402 1687.5,1562.5 r270 bottom
R336 "10k" CR1005-0402 1675,1137.5 r270 bottom
R337 "22k" CR1005-0402 1637.5,1137.5 r270 bottom
R338 "402k" CR1005-0402 1637.5,1562.5 r90 bottom
R339 "10k" CR1005-0402 1600,1137.5 r90 bottom
R340 "301k" CR1005-0402 1600,1562.5 r270 bottom
R341 "NL" CR1005-0402 1562.5,1562.5 r270 bottom
R342 "10k" CR1005-0402 1507.5,1387.5 r0 bottom
R343 "1.91k" CR1005-0402 1507.5,1350 r180 bottom
R344 "10k" CR1005-0402 1525,1562.5 r90 bottom
R345 "22k" CR1005-0402 1425,1350 r270 bottom
R346 "3K" CR1005-0402 1350,-1275 r0 bottom
R347 "30K" CR1005-0402 1350,-1175 r180 bottom
R348 "10m" CR1608-0603 1350,-425 r90 bottom
R349 "10m" CR1608-0603 1350,-200 r90 bottom
R350 "10m" CR1608-0603 1350,-25 r90 bottom
R351 "10m" CR1608-0603 1350,200 r90 bottom
R352 "1k" CR1608-0603 877.5,375 r270 bottom
R353 "49.9" CR1005-0402 675,-25 r180 bottom
R354 "49.9" CR1005-0402 675,25 r180 bottom
R355 "10k" CR1005-0402 575,1062.5 r0 bottom
R356 "10" CR1005-0402 600,-987.5 r270 bottom
R357 "100" CR1005-0402 500,-375 r270 bottom
R358 "4.99k" CR1005-0402 362.04,962.5 r0 bottom
R359 "10" CR1005-0402 287.5,850 r90 bottom
R360 "15K" CR1005-0402 150,1012.5 r0 bottom
R361 "10k" CR1005-0402 150,1062.5 r0 bottom
R362 "10k" CR1005-0402 150,1112.5 r0 bottom
R363 "15K" CR1005-0402 150,1162.5 r180 bottom
R364 "4.99K" CR1005-0402 112.5,-1562.5 r270 bottom value=4.99k
R365 "4.7k" CR1005-0402 98.43,531.5 r90 bottom
R366 "4.7k" CR1005-0402 59.06,531.5 r90 bottom
R367 "4.7k" CR1005-0402 19.69,531.5 r90 bottom
R368 "NL" CR1005-0402 -100,1225 r180 bottom
R369 "4.7k" CR1005-0402 -19.69,531.5 r90 bottom
R370 "NL" CR1005-0402 -100,1187.5 r180 bottom
R371 "100" CR1005-0402 -59.06,531.5 r270 bottom
R372 "100" CR1005-0402 -98.43,531.5 r270 bottom
R373 "1.0k" CR1005-0402 -100,1299.75 r0 bottom
R374 "100" CR1005-0402 -137.8,531.5 r270 bottom
R375 "100" CR1005-0402 -177.17,531.5 r270 bottom
R376 "2k" CR1005-0402 -100,1262.5 r0 bottom
R377 "2k" CR1005-0402 -418.75,-1487.5 r90 bottom
R378 "4.7k" CR1005-0402 -362.5,1772.5 r90 bottom
R379 "4.7k" CR1005-0402 600,-525 r0 top
R380 "1.0k" CR1005-0402 -512.5,1772.5 r90 bottom
R381 "4.7k" CR1005-0402 -562.5,1772.5 r90 bottom
R382 "100" CR0603-0201 275,-137.5 r90 bottom
R383 "2.67K" CR1005-0402 -708.66,-98.43 r0 bottom
R384 "1.6K" CR1005-0402 -708.66,29.53 r0 bottom
R385 "1.6K" CR1005-0402 -708.66,-59.06 r180 bottom
R386 "NL" CR1005-0402 -708.66,68.9 r180 bottom
R387 "2.32K" CR1005-0402 -708.66,108.27 r180 bottom
R388 "1.0k" CR1005-0402 -712.5,1772.5 r90 bottom
R389 "4.7k" CR1005-0402 -762.5,1772.5 r90 bottom
R390 "49.9" CR1005-0402 -937.48,19.69 r0 bottom
R391 "49.9" CR1005-0402 -937.48,78.74 r180 bottom
R392 "22K" CR1005-0402 -937.5,-52.1 r180 bottom
R393 "1.0k" CR1005-0402 -912.5,1772.5 r90 bottom
R394 "4.7k" CR1005-0402 -962.5,1772.5 r90 bottom
R395 "NL" CR1005-0402 -987.5,-1350 r270 bottom
R396 "15" CR1005-0402 -1062.5,-1525 r0 bottom
R397 "NL" CR1005-0402 -1062.5,-1475 r180 bottom
R398 "1.0k" CR1005-0402 -1112.5,1772.5 r90 bottom
R399 "4.7k" CR1005-0402 -1162.5,1772.5 r90 bottom
R400 "1.0k" CR1005-0402 -1312.5,1772.5 r90 bottom
R401A "10K" CR0603-0201 -1608.76,1522.05 r0 bottom (schematic designator R401)
R401B "10K" CR0603-0201 -1608.76,1072.05 r0 bottom (schematic designator R401)
R401C "10K" CR0603-0201 -1608.76,622.05 r0 bottom (schematic designator R401)
R401D "10K" CR0603-0201 -1608.76,172.05 r0 bottom (schematic designator R401)
R401E "10K" CR0603-0201 -1608.76,-277.46 r0 bottom (schematic designator R401)
R401F "10K" CR0603-0201 -1608.76,-727.95 r0 bottom (schematic designator R401)
R401G "10K" CR0603-0201 -1608.76,-1177.95 r0 bottom (schematic designator R401)
R401H "10K" CR0603-0201 -1608.76,-1627.95 r0 bottom (schematic designator R401)
R402A "10K" CR0603-0201 -1608.76,1600.79 r180 bottom (schematic designator R402)
R402B "10K" CR0603-0201 -1608.76,1150.79 r180 bottom (schematic designator R402)
R402C "10K" CR0603-0201 -1608.76,700.79 r180 bottom (schematic designator R402)
R402D "10K" CR0603-0201 -1608.76,250.79 r180 bottom (schematic designator R402)
R402E "10K" CR0603-0201 -1608.76,-199.21 r180 bottom (schematic designator R402)
R402F "10K" CR0603-0201 -1608.76,-649.21 r180 bottom (schematic designator R402)
R402G "10K" CR0603-0201 -1608.76,-1099.21 r180 bottom (schematic designator R402)
R402H "10K" CR0603-0201 -1608.76,-1549.21 r180 bottom (schematic designator R402)
R417A "10K" CR0603-0201 -1670.38,1541.73 r180 bottom (schematic designator R417)
R417B "10K" CR0603-0201 -1670.38,1091.73 r180 bottom (schematic designator R417)
R417C "10K" CR0603-0201 -1670.38,641.73 r180 bottom (schematic designator R417)
R417D "10K" CR0603-0201 -1670.38,191.73 r180 bottom (schematic designator R417)
R417E "10K" CR0603-0201 -1670.38,-258.27 r180 bottom (schematic designator R417)
R417F "10K" CR0603-0201 -1670.38,-708.27 r180 bottom (schematic designator R417)
R417G "10K" CR0603-0201 -1670.38,-1158.27 r180 bottom (schematic designator R417)
R417H "10K" CR0603-0201 -1670.38,-1608.27 r180 bottom (schematic designator R417)
R418A "NL" CR0603-0201 -1670.38,1600.79 r0 bottom (schematic designator R418)
R418B "NL" CR0603-0201 -1670.38,1150.79 r0 bottom (schematic designator R418)
R418C "NL" CR0603-0201 -1670.38,700.79 r0 bottom (schematic designator R418)
R418D "NL" CR0603-0201 -1670.38,250.79 r0 bottom (schematic designator R418)
R418E "NL" CR0603-0201 -1670.38,-199.21 r0 bottom (schematic designator R418)
R418F "NL" CR0603-0201 -1670.38,-649.21 r0 bottom (schematic designator R418)
R418G "NL" CR0603-0201 -1670.38,-1099.21 r0 bottom (schematic designator R418)
R418H "NL" CR0603-0201 -1670.38,-1549.21 r0 bottom (schematic designator R418)
R419A "10K" CR0603-0201 -1670.38,1620.47 r0 bottom (schematic designator R419)
R419B "10K" CR0603-0201 -1670.38,1170.47 r0 bottom (schematic designator R419)
R419C "10K" CR0603-0201 -1670.38,720.47 r0 bottom (schematic designator R419)
R419D "10K" CR0603-0201 -1670.38,270.47 r0 bottom (schematic designator R419)
R419E "10K" CR0603-0201 -1670.38,-179.53 r0 bottom (schematic designator R419)
R419F "10K" CR0603-0201 -1670.38,-629.53 r0 bottom (schematic designator R419)
R419G "10K" CR0603-0201 -1670.38,-1079.53 r0 bottom (schematic designator R419)
R419H "10K" CR0603-0201 -1670.38,-1529.53 r0 bottom (schematic designator R419)
R457A "10K" CR0603-0201 -1716.73,1495.38 r90 bottom (schematic designator R457)
R457B "10K" CR0603-0201 -1716.73,1045.38 r90 bottom (schematic designator R457)
R457C "10K" CR0603-0201 -1716.73,595.38 r90 bottom (schematic designator R457)
R457D "10K" CR0603-0201 -1716.73,145.38 r90 bottom (schematic designator R457)
R457E "10K" CR0603-0201 -1716.73,-304.62 r90 bottom (schematic designator R457)
R457F "10K" CR0603-0201 -1716.73,-754.62 r90 bottom (schematic designator R457)
R457G "10K" CR0603-0201 -1716.73,-1204.62 r90 bottom (schematic designator R457)
R457H "10K" CR0603-0201 -1716.73,-1654.62 r90 bottom (schematic designator R457)
R473A "10K" CR0603-0201 -1736.42,1495.38 r90 bottom (schematic designator R473)
R473B "10K" CR0603-0201 -1736.42,1045.38 r90 bottom (schematic designator R473)
R473C "10K" CR0603-0201 -1736.42,595.38 r90 bottom (schematic designator R473)
R473D "10K" CR0603-0201 -1736.42,145.38 r90 bottom (schematic designator R473)
R473E "10K" CR0603-0201 -1736.42,-304.62 r90 bottom (schematic designator R473)
R473F "10K" CR0603-0201 -1736.42,-754.62 r90 bottom (schematic designator R473)
R473G "10K" CR0603-0201 -1736.42,-1204.62 r90 bottom (schematic designator R473)
R473H "10K" CR0603-0201 -1736.42,-1654.62 r90 bottom (schematic designator R473)
R537A "10k" CR1608-0603 -2137.5,1487.5 r270 bottom (schematic designator R537)
R537B "10k" CR1608-0603 -2137.5,1037.5 r270 bottom (schematic designator R537)
R537C "10k" CR1608-0603 -2137.5,587.5 r270 bottom (schematic designator R537)
R537D "10k" CR1608-0603 -2137.5,137.5 r270 bottom (schematic designator R537)
R537E "10k" CR1608-0603 -2137.5,-312.5 r270 bottom (schematic designator R537)
R537F "10k" CR1608-0603 -2137.5,-762.5 r270 bottom (schematic designator R537)
R537G "10k" CR1608-0603 -2137.5,-1212.5 r270 bottom (schematic designator R537)
R537H "10k" CR1608-0603 -2137.5,-1662.5 r270 bottom (schematic designator R537)
R538A "10k" CR1608-0603 -2137.5,1700 r270 bottom (schematic designator R538)
R538B "10k" CR1608-0603 -2137.5,1250 r270 bottom (schematic designator R538)
R538C "10k" CR1608-0603 -2137.5,800 r270 bottom (schematic designator R538)
R538D "10k" CR1608-0603 -2137.5,350 r270 bottom (schematic designator R538)
R538E "10k" CR1608-0603 -2137.5,-100 r270 bottom (schematic designator R538)
R538F "10k" CR1608-0603 -2137.5,-550 r270 bottom (schematic designator R538)
R538G "10k" CR1608-0603 -2137.5,-1000 r270 bottom (schematic designator R538)
R538H "10k" CR1608-0603 -2137.5,-1450 r270 bottom (schematic designator R538)
R553A "10M" CR0603-0201 -2243.75,1562.5 r0 bottom (schematic designator R553)
R553B "10M" CR0603-0201 -2243.75,1112.5 r0 bottom (schematic designator R553)
R553C "10M" CR0603-0201 -2243.75,662.5 r0 bottom (schematic designator R553)
R553D "10M" CR0603-0201 -2243.75,212.5 r0 bottom (schematic designator R553)
R553E "10M" CR0603-0201 -2243.75,-237.5 r0 bottom (schematic designator R553)
R553F "10M" CR0603-0201 -2243.75,-687.5 r0 bottom (schematic designator R553)
R553G "10M" CR0603-0201 -2243.75,-1137.5 r0 bottom (schematic designator R553)
R553H "10M" CR0603-0201 -2243.75,-1587.5 r0 bottom (schematic designator R553)
R554A "10M" CR0603-0201 -2243.75,1775 r0 bottom (schematic designator R554)
R554B "10M" CR0603-0201 -2243.75,1325 r0 bottom (schematic designator R554)
R554C "10M" CR0603-0201 -2243.75,875 r0 bottom (schematic designator R554)
R554D "10M" CR0603-0201 -2243.75,425 r0 bottom (schematic designator R554)
R554E "10M" CR0603-0201 -2243.75,-25 r0 bottom (schematic designator R554)
R554F "10M" CR0603-0201 -2243.75,-475 r0 bottom (schematic designator R554)
R554G "10M" CR0603-0201 -2243.75,-925 r0 bottom (schematic designator R554)
R554H "10M" CR0603-0201 -2243.75,-1375 r0 bottom (schematic designator R554)
R569A "10M" CR0603-0201 -2331.25,1775 r0 bottom (schematic designator R569)
R569B "10M" CR0603-0201 -2331.25,1325 r0 bottom (schematic designator R569)
R569C "10M" CR0603-0201 -2331.25,875 r0 bottom (schematic designator R569)
R569D "10M" CR0603-0201 -2331.25,425 r0 bottom (schematic designator R569)
R569E "10M" CR0603-0201 -2331.25,-25 r0 bottom (schematic designator R569)
R569F "10M" CR0603-0201 -2331.25,-475 r0 bottom (schematic designator R569)
R569G "10M" CR0603-0201 -2331.25,-925 r0 bottom (schematic designator R569)
R569H "10M" CR0603-0201 -2331.25,-1375 r0 bottom (schematic designator R569)
R577A "10M" CR0603-0201 -2331.34,1562.5 r0 bottom (schematic designator R577)
R577B "10M" CR0603-0201 -2331.34,1112.5 r0 bottom (schematic designator R577)
R577C "10M" CR0603-0201 -2331.34,662.5 r0 bottom (schematic designator R577)
R577D "10M" CR0603-0201 -2331.34,212.5 r0 bottom (schematic designator R577)
R577E "10M" CR0603-0201 -2331.34,-237.5 r0 bottom (schematic designator R577)
R577F "10M" CR0603-0201 -2331.34,-687.5 r0 bottom (schematic designator R577)
R577G "10M" CR0603-0201 -2331.34,-1137.5 r0 bottom (schematic designator R577)
R577H "10M" CR0603-0201 -2331.34,-1587.5 r0 bottom (schematic designator R577)
R585A "10k" CR1608-0603 -2437.5,1487.5 r270 bottom (schematic designator R585)
R585B "10k" CR1608-0603 -2437.5,1037.5 r270 bottom (schematic designator R585)
R585C "10k" CR1608-0603 -2437.5,587.5 r270 bottom (schematic designator R585)
R585D "10k" CR1608-0603 -2437.5,137.5 r270 bottom (schematic designator R585)
R585E "10k" CR1608-0603 -2437.5,-312.5 r270 bottom (schematic designator R585)
R585F "10k" CR1608-0603 -2437.5,-762.5 r270 bottom (schematic designator R585)
R585G "10k" CR1608-0603 -2437.5,-1212.5 r270 bottom (schematic designator R585)
R585H "10k" CR1608-0603 -2437.5,-1662.5 r270 bottom (schematic designator R585)
R593A "10k" CR1608-0603 -2437.5,1700 r270 bottom (schematic designator R593)
R593B "10k" CR1608-0603 -2437.5,1250 r270 bottom (schematic designator R593)
R593C "10k" CR1608-0603 -2437.5,800 r270 bottom (schematic designator R593)
R593D "10k" CR1608-0603 -2437.5,350 r270 bottom (schematic designator R593)
R593E "10k" CR1608-0603 -2437.5,-100 r270 bottom (schematic designator R593)
R593F "10k" CR1608-0603 -2437.5,-550 r270 bottom (schematic designator R593)
R593G "10k" CR1608-0603 -2437.5,-1000 r270 bottom (schematic designator R593)
R593H "10k" CR1608-0603 -2437.5,-1450 r270 bottom (schematic designator R593)
R601A "10k" CR1608-0603 -2525,1487.5 r270 bottom (schematic designator R601)
R601B "10k" CR1608-0603 -2525,1037.5 r270 bottom (schematic designator R601)
R601C "10k" CR1608-0603 -2525,587.5 r270 bottom (schematic designator R601)
R601D "10k" CR1608-0603 -2525,137.5 r270 bottom (schematic designator R601)
R601E "10k" CR1608-0603 -2525,-312.5 r270 bottom (schematic designator R601)
R601F "10k" CR1608-0603 -2525,-762.5 r270 bottom (schematic designator R601)
R601G "10k" CR1608-0603 -2525,-1212.5 r270 bottom (schematic designator R601)
R601H "10k" CR1608-0603 -2525,-1662.5 r270 bottom (schematic designator R601)
R609A "10k" CR1608-0603 -2525,1700 r270 bottom (schematic designator R609)
R609B "10k" CR1608-0603 -2525,1250 r270 bottom (schematic designator R609)
R609C "10k" CR1608-0603 -2525,800 r270 bottom (schematic designator R609)
R609D "10k" CR1608-0603 -2525,350 r270 bottom (schematic designator R609)
R609E "10k" CR1608-0603 -2525,-100 r270 bottom (schematic designator R609)
R609F "10k" CR1608-0603 -2525,-550 r270 bottom (schematic designator R609)
R609G "10k" CR1608-0603 -2525,-1000 r270 bottom (schematic designator R609)
R609H "10k" CR1608-0603 -2525,-1450 r270 bottom (schematic designator R609)
R617A "10M" CR0603-0201 -2631.25,1562.5 r0 bottom (schematic designator R617)
R617B "10M" CR0603-0201 -2631.25,1112.5 r0 bottom (schematic designator R617)
R617C "10M" CR0603-0201 -2631.25,662.5 r0 bottom (schematic designator R617)
R617D "10M" CR0603-0201 -2631.25,212.5 r0 bottom (schematic designator R617)
R617E "10M" CR0603-0201 -2631.25,-237.5 r0 bottom (schematic designator R617)
R617F "10M" CR0603-0201 -2631.25,-687.5 r0 bottom (schematic designator R617)
R617G "10M" CR0603-0201 -2631.25,-1137.5 r0 bottom (schematic designator R617)
R617H "10M" CR0603-0201 -2631.25,-1587.5 r0 bottom (schematic designator R617)
R618A "10M" CR0603-0201 -2631.25,1775 r0 bottom (schematic designator R618)
R618B "10M" CR0603-0201 -2631.25,1325 r0 bottom (schematic designator R618)
R618C "10M" CR0603-0201 -2631.25,875 r0 bottom (schematic designator R618)
R618D "10M" CR0603-0201 -2631.25,425 r0 bottom (schematic designator R618)
R618E "10M" CR0603-0201 -2631.25,-25 r0 bottom (schematic designator R618)
R618F "10M" CR0603-0201 -2631.25,-475 r0 bottom (schematic designator R618)
R618G "10M" CR0603-0201 -2631.25,-925 r0 bottom (schematic designator R618)
R618H "10M" CR0603-0201 -2631.25,-1375 r0 bottom (schematic designator R618)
